Omron CX-Programmer project NewProject (CX-Programmer 9.03)

# PLC NewPLC1: CJ1M CPU11
I/O table (CPU CJ1M-CPU11): rack 0 slot 0 CJ1W-ID211; rack 0 slot 1 CJ1W-ID211; rack 0 slot 2 CJ1W-SCU21-V1

## Global symbols (name address type ; comment)
1509.05 BOOL  ; Communication Port #1 TXDU Instruction Executing Flag
1519.05 BOOL  ; Communication Port #2 TXDU Instruction Executing Flag
A202.00 BOOL  ; Communications Port #1 Enabled Flag
A202.01 BOOL  ; Communications Port #2 Enabled Flag
A392.05 BOOL  ; RS-232C Port's Send Ready Flag
D5050 CHANNEL  ; Part Counter Word 1
D5051 CHANNEL  ; Part Counter Word 2
D800 CHANNEL  ; Communication Port #1 Control Word 1
D801 CHANNEL  ; Communication Port #1 Control Word 2
D900 CHANNEL  ; Communication Port #2 Control Word 1
D901 CHANNEL  ; Communication Port #2 Control Word 2

## Program NewProgram1 (cyclic task 0)
; The format of the structure is based upon the following format (explained in Section 8 of Datamax I-Class Programmer's Manual): / abcdeeeffffggggjj...j / a = Rotation (The first field of a header is a single ASCII character that selects the degree of rotation for the data / to be printed on a label. Valid rotation values are clockwise: 1 (0º); 2 (90º); 3 (180º); and, 4 (270º). / Figure 8-1 shows the direction and amount of rotation, relative to the label feed direction, where / the bottom left corner is the pivot point.) / b = Fonts, Bar Codes, Graphics and Images (The second field (b) determines how the rest of the fields are interpreted, as shown in the table / below. Values 0 through 9 select human-readable fonts. 0 through 8 will select standard Datamax / fonts; value 9 selects the CG Triumvirate smooth scalable font (internal) or scalable fonts. When 9 / is used to select a scalable font, the font size (font I.D. number) is chosen by entering a value in the / height field eee. / Values A through z select bar codes. Values A through T (uppercase) will print bar codes with / human-readable interpretations. Values a through z (lowercase) will print bar codes only. / Value W requires two additional characters to specify the Bar Code/Font ID. / A font field value X selects a drawing object (line, box, circle or polygon), and field value Y is / used to print an image stored in a module. / b Font Field Value Interpretation / 0-9 - Font / A-T - Bar code with human readable text. / a-z - Bar code without human readable text. / Wxx - Bar code/Font expansion / X - Line, box, polygon, circle / Y - Image) / c = Width Multiplier (Values 1-9, A-Z, and a-z represent multiplication factors from 1 – 61, respectively. For humanreadable / fonts, the width multiplier represents the number of times the selected font dot tables are / multiplied and has no effect on the character height. For bar codes, this character specifies the wide / bar width or ratio at a resolution that is dependent upon the printer model. See Appendix F for / default values.) / d = Height Multiplier (The height multiplier has the same range and function as the width multiplier (c), but vertical. / When used in the context of bar codes, this field is the ratio denominator, or the small bar (module) / width. Values 1-9, A-Z, and a-z will give a narrow bar width of one dot (dot size = 1/printhead / resolution) to dots. The narrow bar width resolution and range are dependent upon the print head / resolution, see Appendix K. A “dot multiplier” command can also be used to change the printed / dot size (see Label Formatting Command ‘D’ and Appendix F).) / eee = Bar Code Height (Font Size/Selection) (This field has interpretations dependent upon the value of the font b field, as shown below. / b Font Field Value / eee Field Range / eee Field Interpretation / 0-8 / 000 / Not used – Internal bitmapped font / 9 / 000-999, A04-A72, S00-S9z, / U00-U9z, u00-u9z / Font height; Font selection / A-T / 000-999 / Bar code height (with human readable) / a-z / 000-999 / Bar code height / Wxx / 000-999 / Bar code height (with human readable) / X,Y / 000 / Not used) / ffff = Row Position (The lower left corner of a label is considered the “home position” (see Figure 8-1). The row / position field is a vertical coordinate that determines how far above the home position the data is to / be printed. Field data is interpreted in hundredths of an inch or tenths of millimeters.) / gggg = Column Position (This field is a horizontal coordinate that determines how far to the right of “home position” the / data will be printed. Appendix G lists the maximum values of the gggg field.) / jj-j = Data Field (The final field contains the data that will actually be printed on the label. A string of data can be up / to 255 characters in length (except when using the PDF417 bar code, which may be up to 3000 / characters long), ending with a carriage return. Characters placed in the data field will be printed as / long as they fall within the physical range of the print head. Consult Appendix K for a listing by / printer.)

### Section Section1

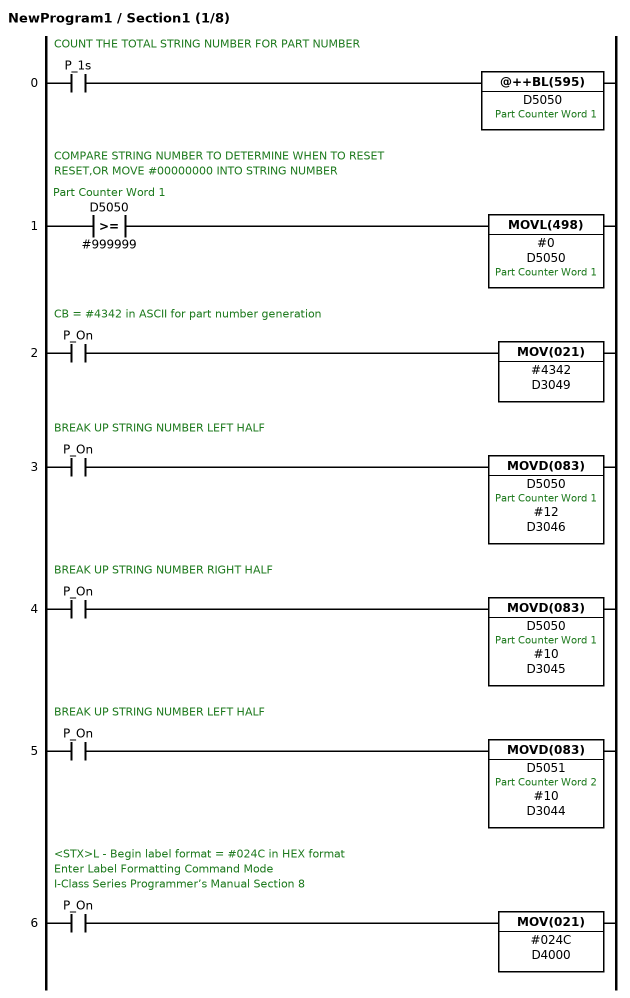
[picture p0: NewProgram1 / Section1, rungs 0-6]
; rung 0: COUNT THE TOTAL STRING NUMBER FOR PART NUMBER
LD P_1s
@++BL(595) D5050  ; Part Counter Word 1
; rung 1: COMPARE STRING NUMBER TO DETERMINE WHEN TO RESET / RESET,OR MOVE #00000000 INTO STRING NUMBER
LD>=L(326) D5050 #999999  ; Part Counter Word 1
MOVL(498) #0 D5050  ; Part Counter Word 1
; rung 2: CB = #4342 in ASCII for part number generation
LD P_On
MOV(021) #4342 D3049
; rung 3: BREAK UP STRING NUMBER LEFT HALF
LD P_On
MOVD(083) D5050 #12 D3046  ; Part Counter Word 1
; rung 4: BREAK UP STRING NUMBER RIGHT HALF
LD P_On
MOVD(083) D5050 #10 D3045  ; Part Counter Word 1
; rung 5: BREAK UP STRING NUMBER LEFT HALF
LD P_On
MOVD(083) D5051 #10 D3044  ; Part Counter Word 2
; rung 6: <STX>L - Begin label format = #024C in HEX format / Enter Label Formatting Command Mode / I-Class Series Programmer’s Manual Section 8
LD P_On
MOV(021) #024C D4000

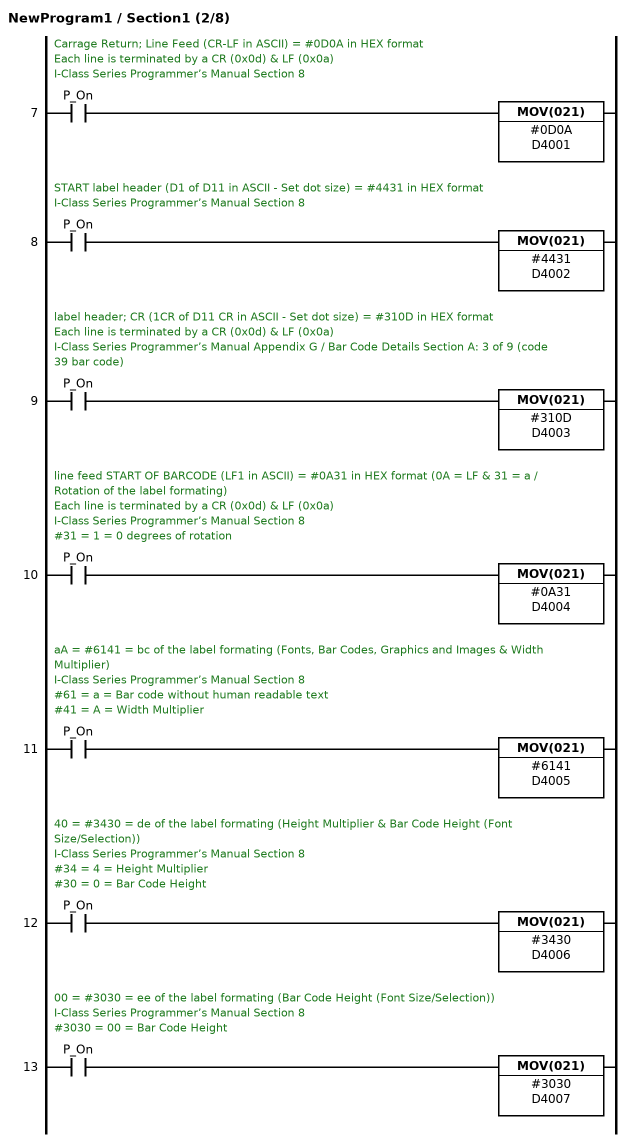
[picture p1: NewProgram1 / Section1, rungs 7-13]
; rung 7: Carrage Return; Line Feed (CR-LF in ASCII) = #0D0A in HEX format / Each line is terminated by a CR (0x0d) & LF (0x0a) / I-Class Series Programmer’s Manual Section 8
LD P_On
MOV(021) #0D0A D4001
; rung 8: START label header (D1 of D11 in ASCII - Set dot size) = #4431 in HEX format / I-Class Series Programmer’s Manual Section 8
LD P_On
MOV(021) #4431 D4002
; rung 9: label header; CR (1CR of D11 CR in ASCII - Set dot size) = #310D in HEX format / Each line is terminated by a CR (0x0d) & LF (0x0a) / I-Class Series Programmer’s Manual Appendix G / Bar Code Details Section A: 3 of 9 (code 39 bar code)
LD P_On
MOV(021) #310D D4003
; rung 10: line feed START OF BARCODE (LF1 in ASCII) = #0A31 in HEX format (0A = LF & 31 = a / Rotation of the label formating) / Each line is terminated by a CR (0x0d) & LF (0x0a) / I-Class Series Programmer’s Manual Section 8 / #31 = 1 = 0 degrees of rotation
LD P_On
MOV(021) #0A31 D4004
; rung 11: aA = #6141 = bc of the label formating (Fonts, Bar Codes, Graphics and Images & Width Multiplier) / I-Class Series Programmer’s Manual Section 8 / #61 = a = Bar code without human readable text / #41 = A = Width Multiplier
LD P_On
MOV(021) #6141 D4005
; rung 12: 40 = #3430 = de of the label formating (Height Multiplier & Bar Code Height (Font Size/Selection)) / I-Class Series Programmer’s Manual Section 8 / #34 = 4 = Height Multiplier / #30 = 0 = Bar Code Height
LD P_On
MOV(021) #3430 D4006
; rung 13: 00 = #3030 = ee of the label formating (Bar Code Height (Font Size/Selection)) / I-Class Series Programmer’s Manual Section 8 / #3030 = 00 = Bar Code Height
LD P_On
MOV(021) #3030 D4007

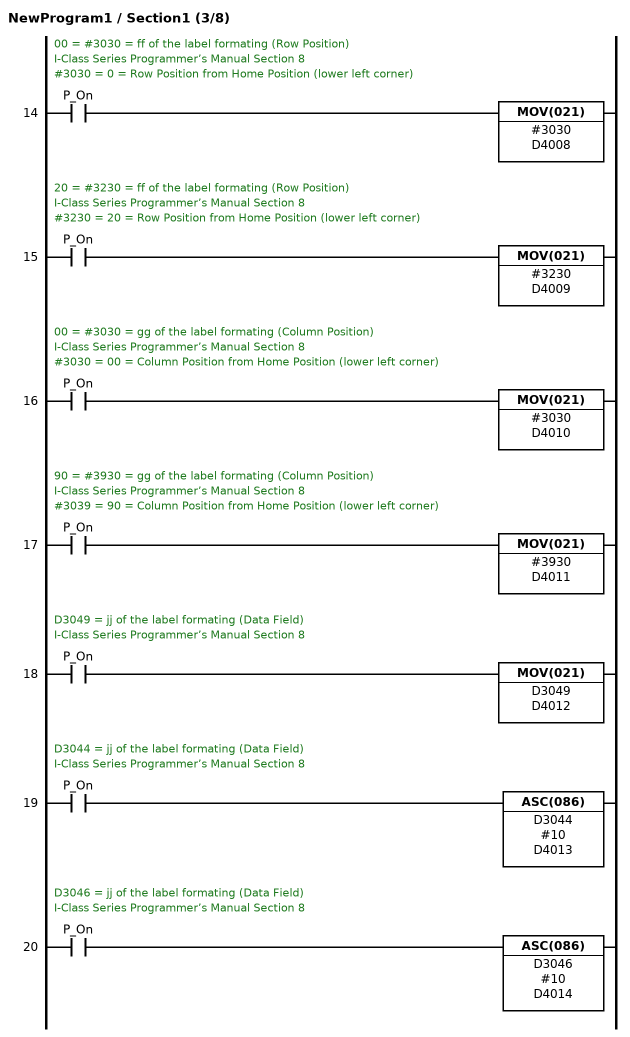
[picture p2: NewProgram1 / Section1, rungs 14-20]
; rung 14: 00 = #3030 = ff of the label formating (Row Position) / I-Class Series Programmer’s Manual Section 8 / #3030 = 0 = Row Position from Home Position (lower left corner)
LD P_On
MOV(021) #3030 D4008
; rung 15: 20 = #3230 = ff of the label formating (Row Position) / I-Class Series Programmer’s Manual Section 8 / #3230 = 20 = Row Position from Home Position (lower left corner)
LD P_On
MOV(021) #3230 D4009
; rung 16: 00 = #3030 = gg of the label formating (Column Position) / I-Class Series Programmer’s Manual Section 8 / #3030 = 00 = Column Position from Home Position (lower left corner)
LD P_On
MOV(021) #3030 D4010
; rung 17: 90 = #3930 = gg of the label formating (Column Position) / I-Class Series Programmer’s Manual Section 8 / #3039 = 90 = Column Position from Home Position (lower left corner)
LD P_On
MOV(021) #3930 D4011
; rung 18: D3049 = jj of the label formating (Data Field) / I-Class Series Programmer’s Manual Section 8
LD P_On
MOV(021) D3049 D4012
; rung 19: D3044 = jj of the label formating (Data Field) / I-Class Series Programmer’s Manual Section 8
LD P_On
ASC(086) D3044 #10 D4013
; rung 20: D3046 = jj of the label formating (Data Field) / I-Class Series Programmer’s Manual Section 8
LD P_On
ASC(086) D3046 #10 D4014

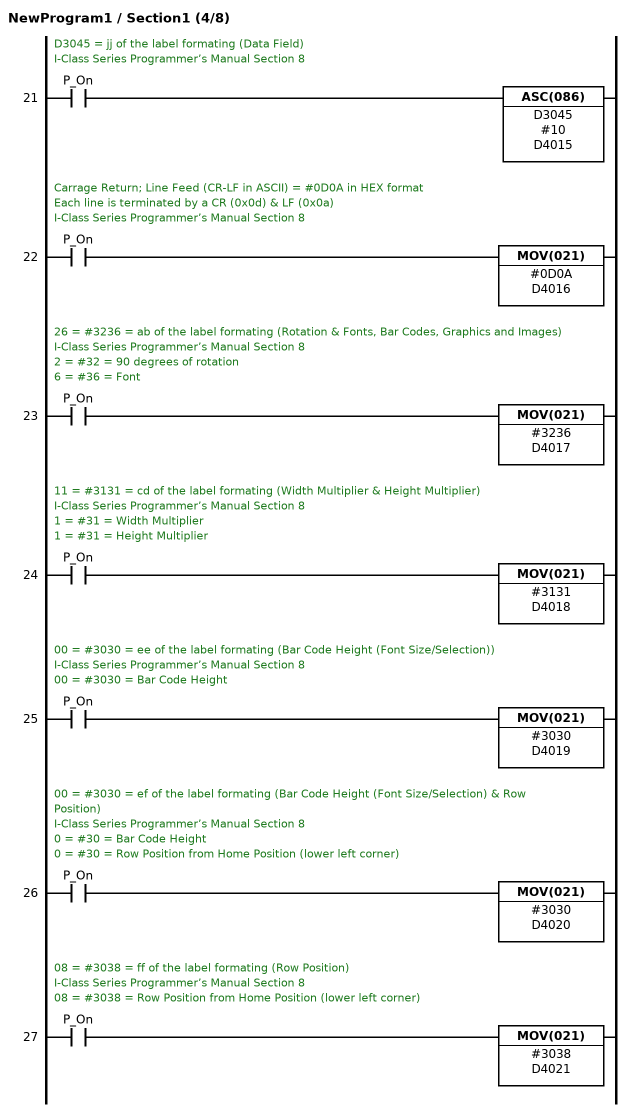
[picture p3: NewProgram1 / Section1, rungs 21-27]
; rung 21: D3045 = jj of the label formating (Data Field) / I-Class Series Programmer’s Manual Section 8
LD P_On
ASC(086) D3045 #10 D4015
; rung 22: Carrage Return; Line Feed (CR-LF in ASCII) = #0D0A in HEX format / Each line is terminated by a CR (0x0d) & LF (0x0a) / I-Class Series Programmer’s Manual Section 8
LD P_On
MOV(021) #0D0A D4016
; rung 23: 26 = #3236 = ab of the label formating (Rotation & Fonts, Bar Codes, Graphics and Images) / I-Class Series Programmer’s Manual Section 8 / 2 = #32 = 90 degrees of rotation / 6 = #36 = Font
LD P_On
MOV(021) #3236 D4017
; rung 24: 11 = #3131 = cd of the label formating (Width Multiplier & Height Multiplier) / I-Class Series Programmer’s Manual Section 8 / 1 = #31 = Width Multiplier / 1 = #31 = Height Multiplier
LD P_On
MOV(021) #3131 D4018
; rung 25: 00 = #3030 = ee of the label formating (Bar Code Height (Font Size/Selection)) / I-Class Series Programmer’s Manual Section 8 / 00 = #3030 = Bar Code Height
LD P_On
MOV(021) #3030 D4019
; rung 26: 00 = #3030 = ef of the label formating (Bar Code Height (Font Size/Selection) & Row Position) / I-Class Series Programmer’s Manual Section 8 / 0 = #30 = Bar Code Height / 0 = #30 = Row Position from Home Position (lower left corner)
LD P_On
MOV(021) #3030 D4020
; rung 27: 08 = #3038 = ff of the label formating (Row Position) / I-Class Series Programmer’s Manual Section 8 / 08 = #3038 = Row Position from Home Position (lower left corner)
LD P_On
MOV(021) #3038 D4021

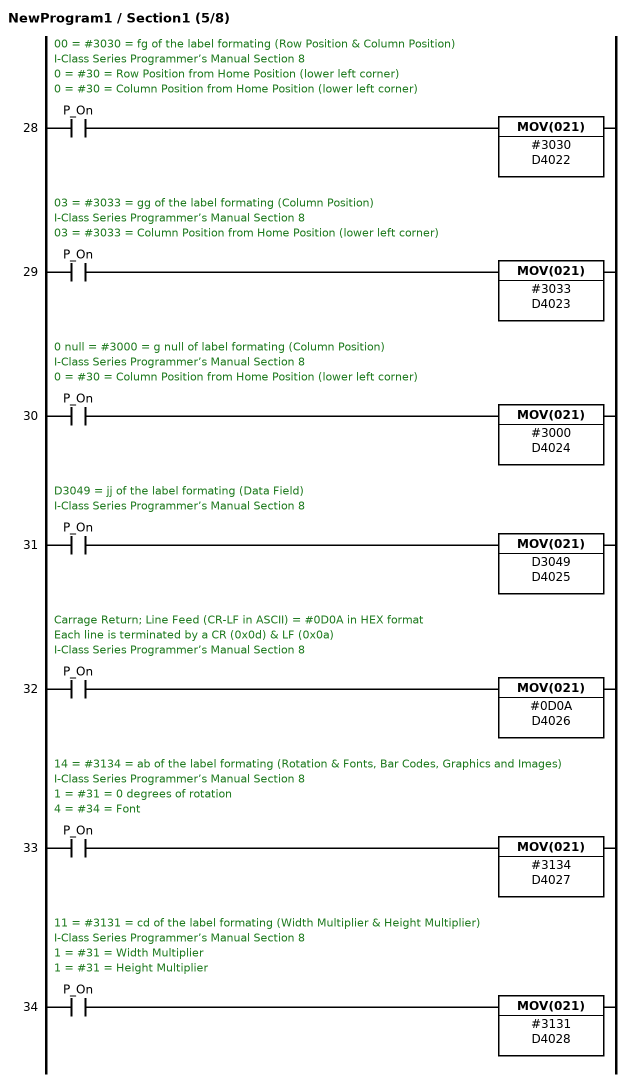
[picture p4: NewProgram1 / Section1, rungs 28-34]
; rung 28: 00 = #3030 = fg of the label formating (Row Position & Column Position) / I-Class Series Programmer’s Manual Section 8 / 0 = #30 = Row Position from Home Position (lower left corner) / 0 = #30 = Column Position from Home Position (lower left corner)
LD P_On
MOV(021) #3030 D4022
; rung 29: 03 = #3033 = gg of the label formating (Column Position) / I-Class Series Programmer’s Manual Section 8 / 03 = #3033 = Column Position from Home Position (lower left corner)
LD P_On
MOV(021) #3033 D4023
; rung 30: 0 null = #3000 = g null of label formating (Column Position) / I-Class Series Programmer’s Manual Section 8 / 0 = #30 = Column Position from Home Position (lower left corner)
LD P_On
MOV(021) #3000 D4024
; rung 31: D3049 = jj of the label formating (Data Field) / I-Class Series Programmer’s Manual Section 8
LD P_On
MOV(021) D3049 D4025
; rung 32: Carrage Return; Line Feed (CR-LF in ASCII) = #0D0A in HEX format / Each line is terminated by a CR (0x0d) & LF (0x0a) / I-Class Series Programmer’s Manual Section 8
LD P_On
MOV(021) #0D0A D4026
; rung 33: 14 = #3134 = ab of the label formating (Rotation & Fonts, Bar Codes, Graphics and Images) / I-Class Series Programmer’s Manual Section 8 / 1 = #31 = 0 degrees of rotation / 4 = #34 = Font
LD P_On
MOV(021) #3134 D4027
; rung 34: 11 = #3131 = cd of the label formating (Width Multiplier & Height Multiplier) / I-Class Series Programmer’s Manual Section 8 / 1 = #31 = Width Multiplier / 1 = #31 = Height Multiplier
LD P_On
MOV(021) #3131 D4028

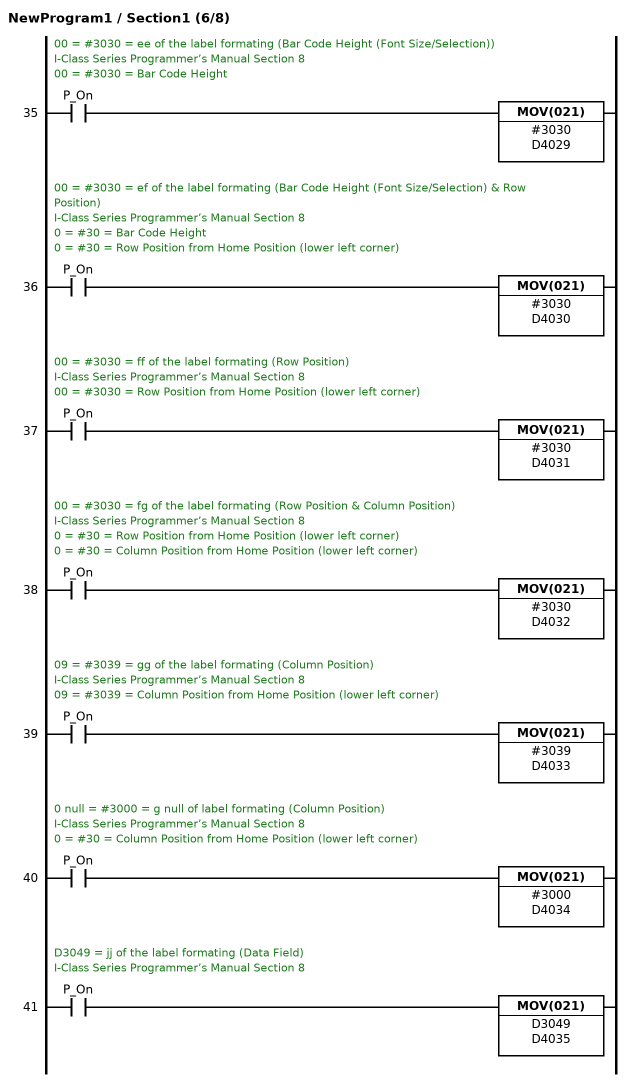
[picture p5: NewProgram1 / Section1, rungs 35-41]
; rung 35: 00 = #3030 = ee of the label formating (Bar Code Height (Font Size/Selection)) / I-Class Series Programmer’s Manual Section 8 / 00 = #3030 = Bar Code Height
LD P_On
MOV(021) #3030 D4029
; rung 36: 00 = #3030 = ef of the label formating (Bar Code Height (Font Size/Selection) & Row Position) / I-Class Series Programmer’s Manual Section 8 / 0 = #30 = Bar Code Height / 0 = #30 = Row Position from Home Position (lower left corner)
LD P_On
MOV(021) #3030 D4030
; rung 37: 00 = #3030 = ff of the label formating (Row Position) / I-Class Series Programmer’s Manual Section 8 / 00 = #3030 = Row Position from Home Position (lower left corner)
LD P_On
MOV(021) #3030 D4031
; rung 38: 00 = #3030 = fg of the label formating (Row Position & Column Position) / I-Class Series Programmer’s Manual Section 8 / 0 = #30 = Row Position from Home Position (lower left corner) / 0 = #30 = Column Position from Home Position (lower left corner)
LD P_On
MOV(021) #3030 D4032
; rung 39: 09 = #3039 = gg of the label formating (Column Position) / I-Class Series Programmer’s Manual Section 8 / 09 = #3039 = Column Position from Home Position (lower left corner)
LD P_On
MOV(021) #3039 D4033
; rung 40: 0 null = #3000 = g null of label formating (Column Position) / I-Class Series Programmer’s Manual Section 8 / 0 = #30 = Column Position from Home Position (lower left corner)
LD P_On
MOV(021) #3000 D4034
; rung 41: D3049 = jj of the label formating (Data Field) / I-Class Series Programmer’s Manual Section 8
LD P_On
MOV(021) D3049 D4035

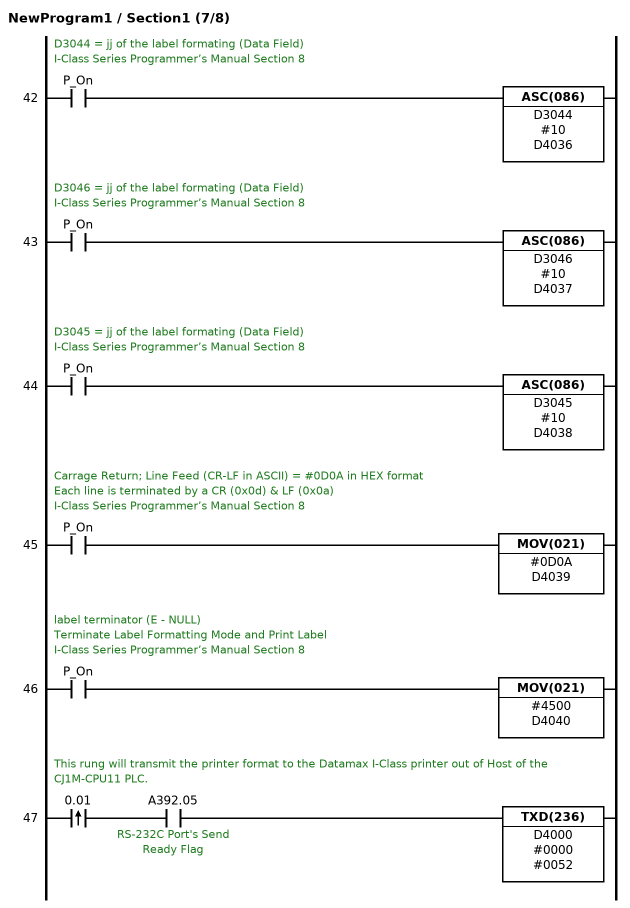
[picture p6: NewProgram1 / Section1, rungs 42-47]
; rung 42: D3044 = jj of the label formating (Data Field) / I-Class Series Programmer’s Manual Section 8
LD P_On
ASC(086) D3044 #10 D4036
; rung 43: D3046 = jj of the label formating (Data Field) / I-Class Series Programmer’s Manual Section 8
LD P_On
ASC(086) D3046 #10 D4037
; rung 44: D3045 = jj of the label formating (Data Field) / I-Class Series Programmer’s Manual Section 8
LD P_On
ASC(086) D3045 #10 D4038
; rung 45: Carrage Return; Line Feed (CR-LF in ASCII) = #0D0A in HEX format / Each line is terminated by a CR (0x0d) & LF (0x0a) / I-Class Series Programmer’s Manual Section 8
LD P_On
MOV(021) #0D0A D4039
; rung 46: label terminator (E - NULL) / Terminate Label Formatting Mode and Print Label / I-Class Series Programmer’s Manual Section 8
LD P_On
MOV(021) #4500 D4040
; rung 47: This rung will transmit the printer format to the Datamax I-Class printer out of Host of the CJ1M-CPU11 PLC.
@LD 0.01
AND A392.05  ; RS-232C Port's Send Ready Flag
TXD(236) D4000 #0000 #0052

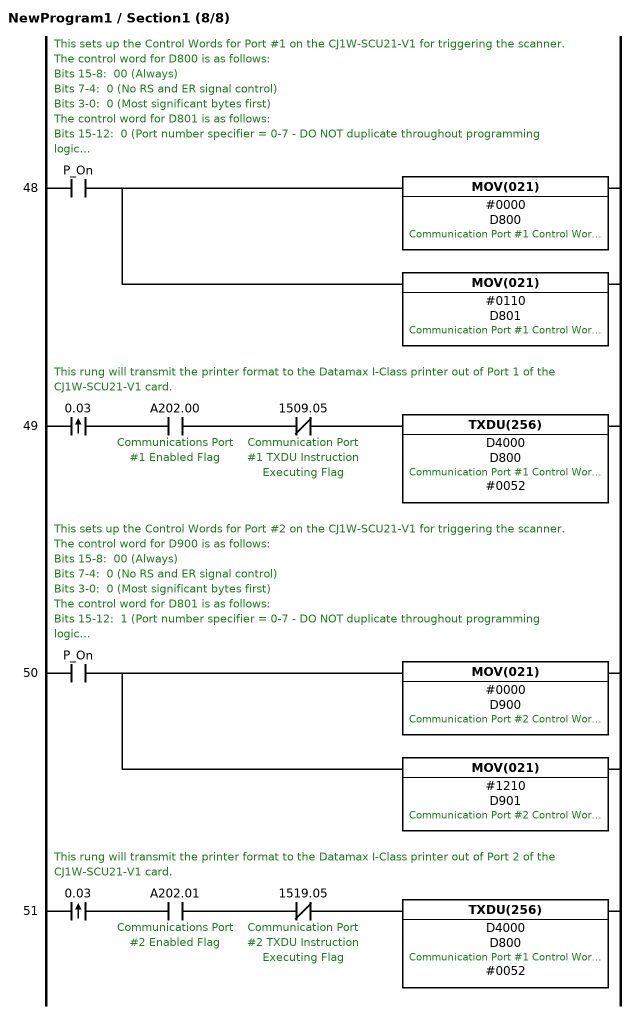
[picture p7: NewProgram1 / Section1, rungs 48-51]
; rung 48: This sets up the Control Words for Port #1 on the CJ1W-SCU21-V1 for triggering the scanner. / The control word for D800 is as follows: / Bits 15-8:  00 (Always) / Bits 7-4:  0 (No RS and ER signal control) / Bits 3-0:  0 (Most significant bytes first) / The control word for D801 is as follows: / Bits 15-12:  0 (Port number specifier = 0-7 - DO NOT duplicate throughout programming logic) / Bits 11-8:  1 (Port 1) / Bits 7-0:  10 (Serial Communications Unit's unit address - unit number + 10 hex)
LD P_On
MOV(021) #0000 D800  ; Communication Port #1 Control Word 1
MOV(021) #0110 D801  ; Communication Port #1 Control Word 2
; rung 49: This rung will transmit the printer format to the Datamax I-Class printer out of Port 1 of the CJ1W-SCU21-V1 card.
@LD 0.03
AND A202.00  ; Communications Port #1 Enabled Flag
ANDNOT 1509.05  ; Communication Port #1 TXDU Instruction Executing Flag
TXDU(256) D4000 D800 #0052  ; Communication Port #1 Control Word 1
; rung 50: This sets up the Control Words for Port #2 on the CJ1W-SCU21-V1 for triggering the scanner. / The control word for D900 is as follows: / Bits 15-8:  00 (Always) / Bits 7-4:  0 (No RS and ER signal control) / Bits 3-0:  0 (Most significant bytes first) / The control word for D801 is as follows: / Bits 15-12:  1 (Port number specifier = 0-7 - DO NOT duplicate throughout programming logic) / Bits 11-8:  2 (Port 2) / Bits 7-0:  10 (Serial Communications Unit's unit address - unit number + 10 hex)
LD P_On
MOV(021) #0000 D900  ; Communication Port #2 Control Word 1
MOV(021) #1210 D901  ; Communication Port #2 Control Word 2
; rung 51: This rung will transmit the printer format to the Datamax I-Class printer out of Port 2 of the CJ1W-SCU21-V1 card.
@LD 0.03
AND A202.01  ; Communications Port #2 Enabled Flag
ANDNOT 1519.05  ; Communication Port #2 TXDU Instruction Executing Flag
TXDU(256) D4000 D800 #0052  ; Communication Port #1 Control Word 1

### Section END
; rung 0
END(001)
